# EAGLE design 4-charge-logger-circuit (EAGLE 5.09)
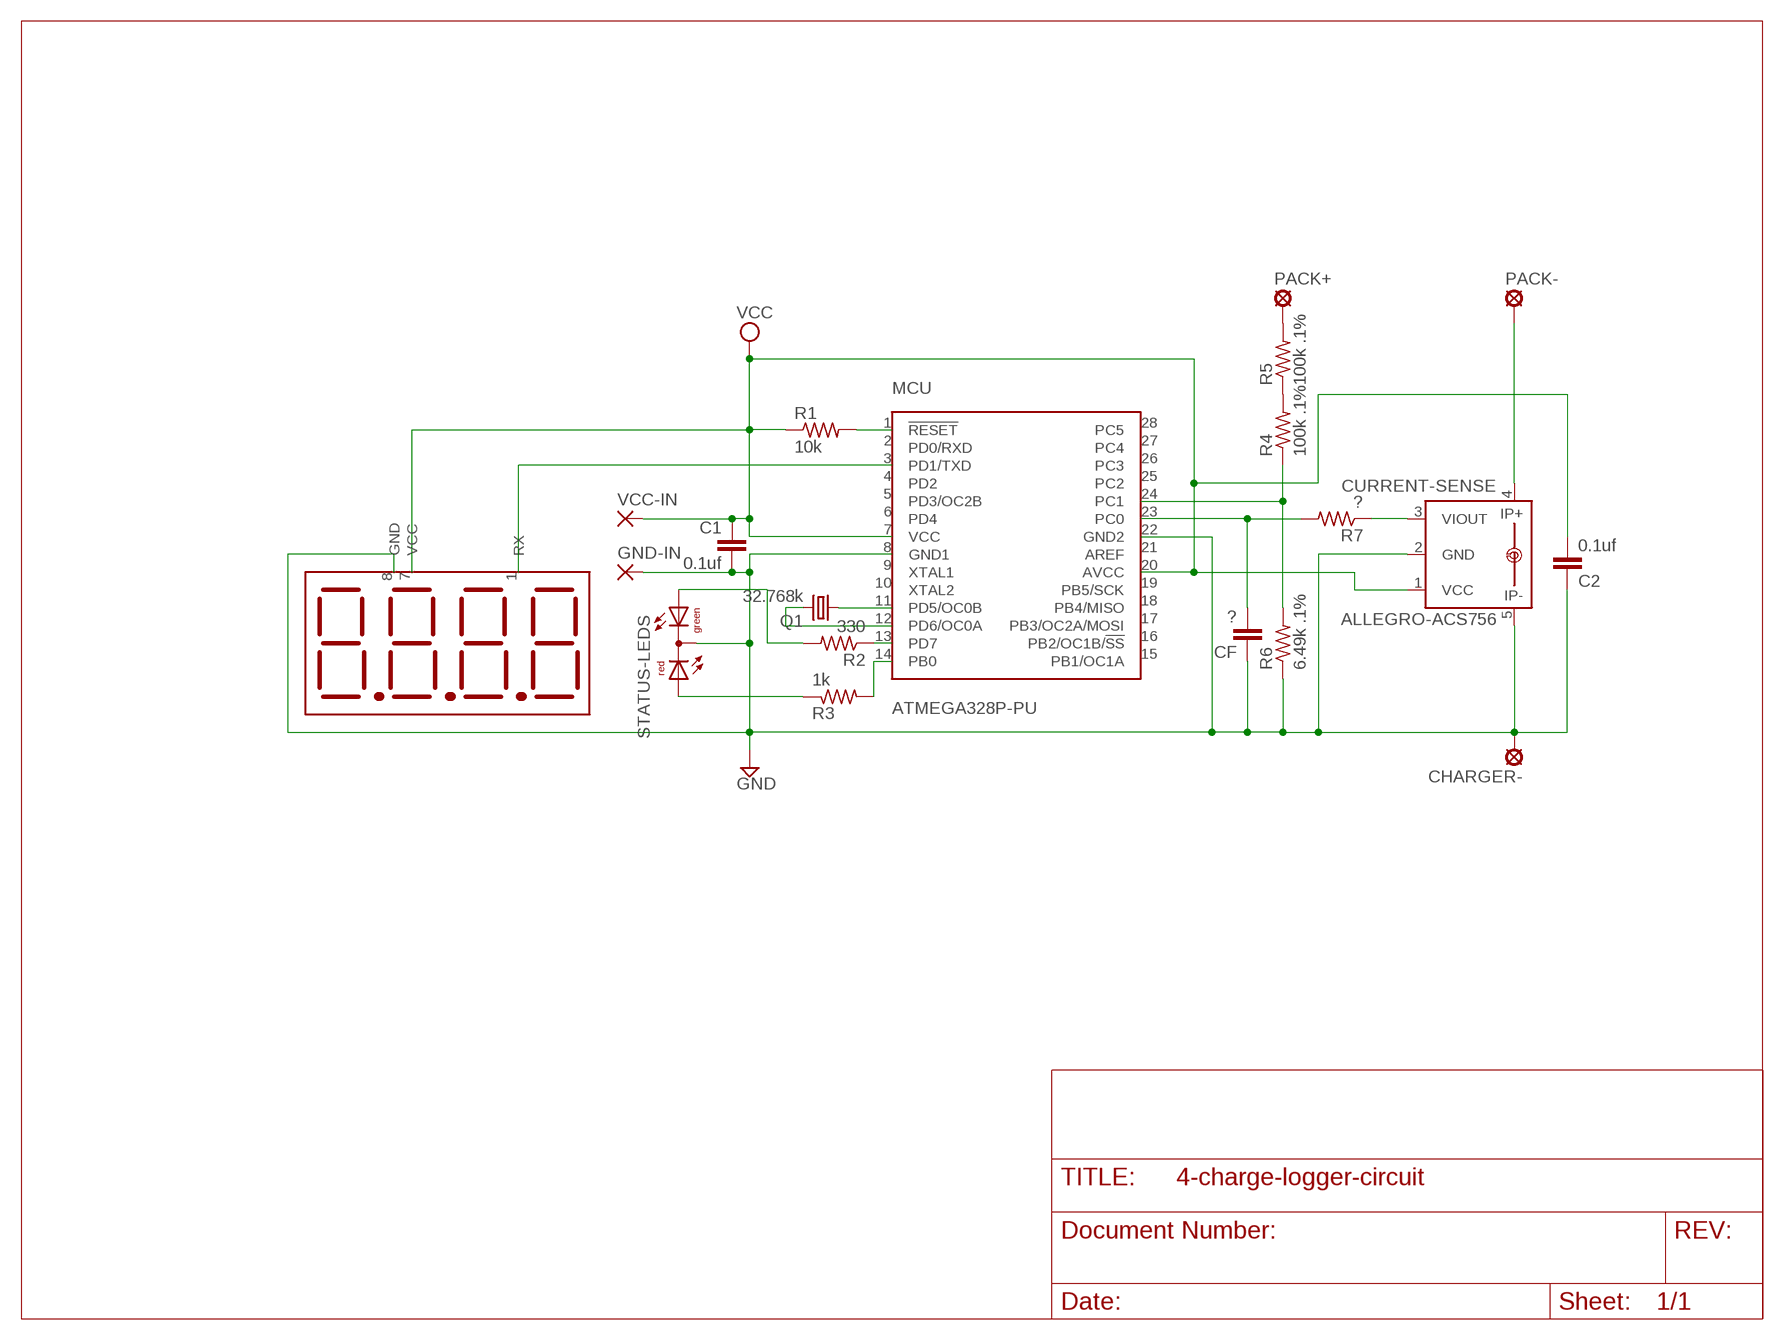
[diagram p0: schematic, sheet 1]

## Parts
C1  0.1uf  C2.5/2  [C2.5-2]
C2  0.1uf  C2.5/2  [C2.5-2]
CF  ?  C2.5/2  [C2.5-2]
CHARGER-  SE14  [SE14]
CURRENT-SENSE  ALLEGRO-ACS756  [ALLEGRO-ACS756]
GND-IN  1,6/0,8  [1,6/0,8]
MCU  ATMEGA328P-PU  [DIL28-3]
PACK+  SE14  [SE14]
PACK-  SE14  [SE14]
Q1  32.768k  CRYSTALTC26V  [TC26V]
R1  10k  R-US_0204/5  [0204/5]
R2  330  R-US_0204/5  [0204/5]
R3  1k  R-US_0204/5  [0204/5]
R4  100k .1%  R-US_R0805  [R0805]
R5  100k .1%  R-US_R0805  [R0805]
R6  6.49k .1%  R-US_R0402  [R0402]
R7  ?  R-US_0204/5  [0204/5]
STATUS-LEDS  DUOLED2X5  [DUOLED2X5]
U$1  4-DIGIT-DISPLAY  [3SIL-OF-8]
VCC-IN  1,6/0,8  [1,6/0,8]

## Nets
GND: C1.2 C2.1 CF.1 CHARGER-.MP CURRENT-SENSE.2(GND) CURRENT-SENSE.5(IP-) GND-IN.1(P) MCU.8(GND1) MCU.22(GND2) R6.1 STATUS-LEDS.K(C) U$1.8(GND)
N$1: MCU.1(!RESET) R1.2
N$2: MCU.12(PD6/OC0A) Q1.2
N$3: MCU.11(PD5/OC0B) Q1.1
N$4: MCU.13(PD7) R2.1
N$5: R3.1 STATUS-LEDS.AR
N$6: R2.2 STATUS-LEDS.AG
N$7: MCU.14(PB0) R3.2
N$8: R4.2 R5.1
N$9: MCU.3(PD1/TXD) U$1.1(RX)
N$10: CF.2 MCU.23(PC0) R7.2
N$11: PACK+.MP R5.2
N$12: CURRENT-SENSE.3(VIOUT) R7.1
N$13: MCU.24(PC1) R4.1 R6.2
N$14: CURRENT-SENSE.4(IP+) PACK-.MP
VCC: C1.1 C2.2 CURRENT-SENSE.1(VCC) MCU.7(VCC) MCU.20(AVCC) R1.1 U$1.7(VCC) VCC-IN.1(P)
Unconnected: MCU.2(PD0/RXD) MCU.4(PD2) MCU.5(PD3/OC2B) MCU.6(PD4) MCU.9(XTAL1) MCU.10(XTAL2) MCU.15(PB1/OC1A) MCU.16(PB2/OC1B/!SS) MCU.17(PB3/OC2A/MOSI) MCU.18(PB4/MISO) MCU.19(PB5/SCK) MCU.21(AREF) MCU.25(PC2) MCU.26(PC3) MCU.27(PC4) MCU.28(PC5)

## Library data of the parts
C1 C2 CF = capacitor-wima:C: CAPACITOR
CHARGER- PACK+ PACK- = solpad:SE14: SOLDER PAD
CURRENT-SENSE = trl:ALLEGRO-ACS756
GND-IN VCC-IN = wirepad:1,6/0,8: THROUGH-HOLE PAD
MCU = trl:ATMEGA328P-PU
Q1 = crystal:CRYSTAL: CRYSTAL
R1-R7 = resistor:R-US_: RESISTOR, American symbol
STATUS-LEDS = led:DUOLED2X5: DUO LED 2 colors, 2.5 x 5 mm, recangle
U$1 = trl:4-DIGIT-DISPLAY

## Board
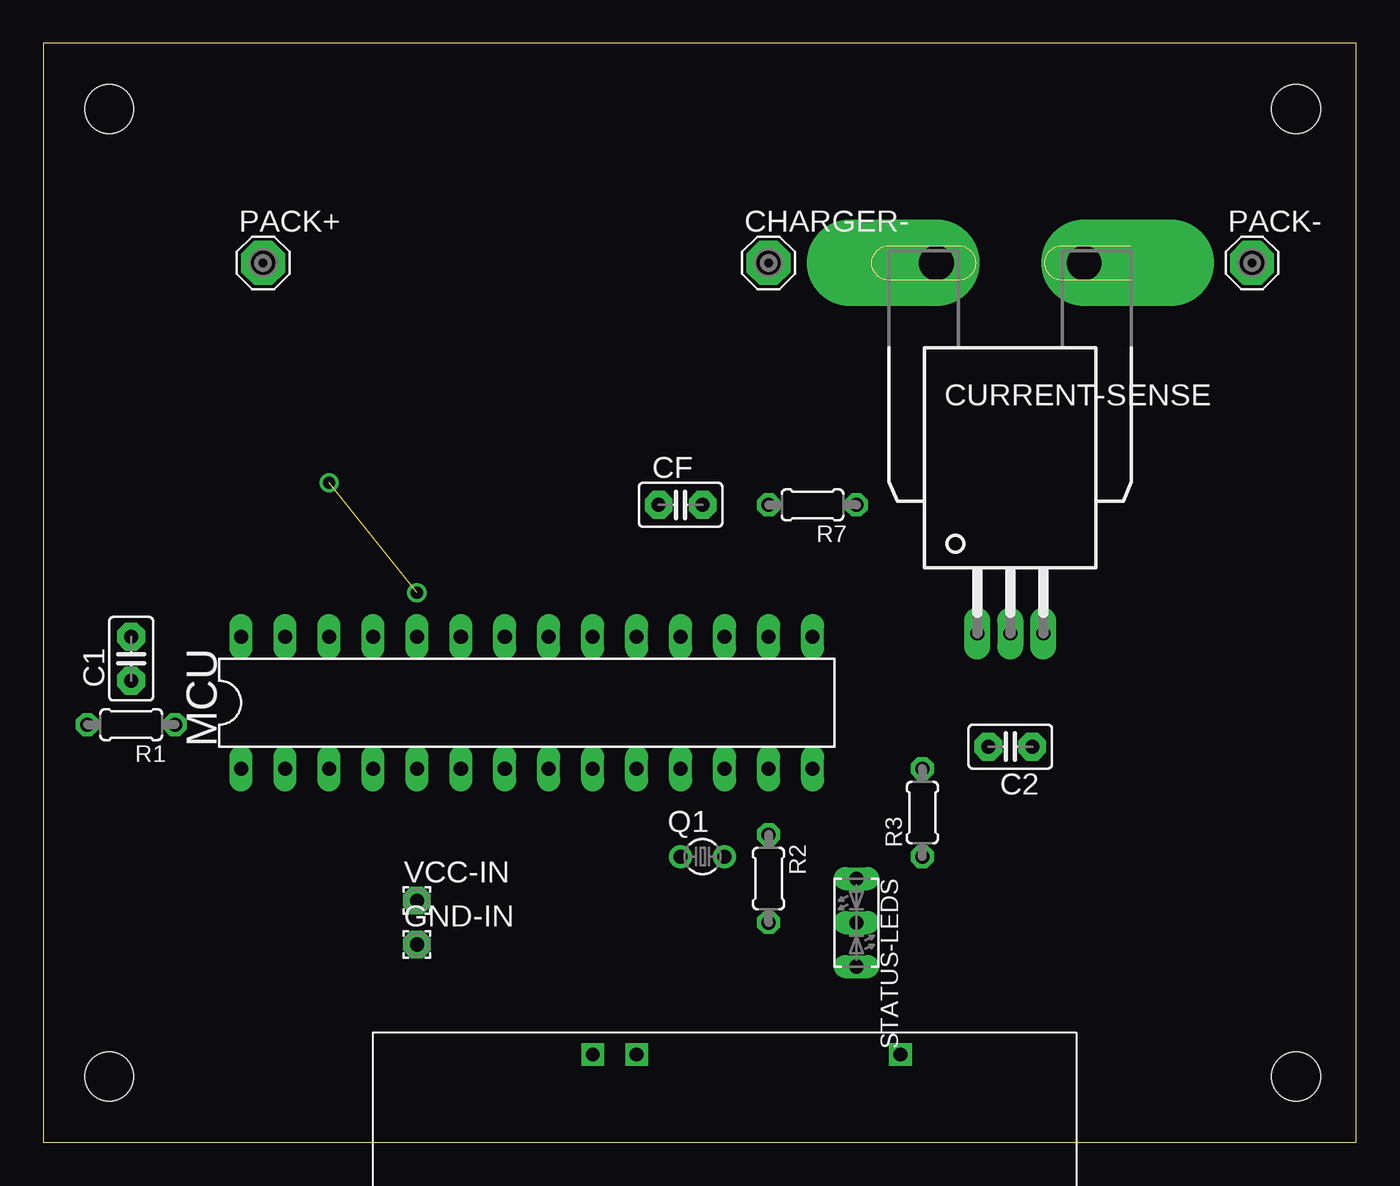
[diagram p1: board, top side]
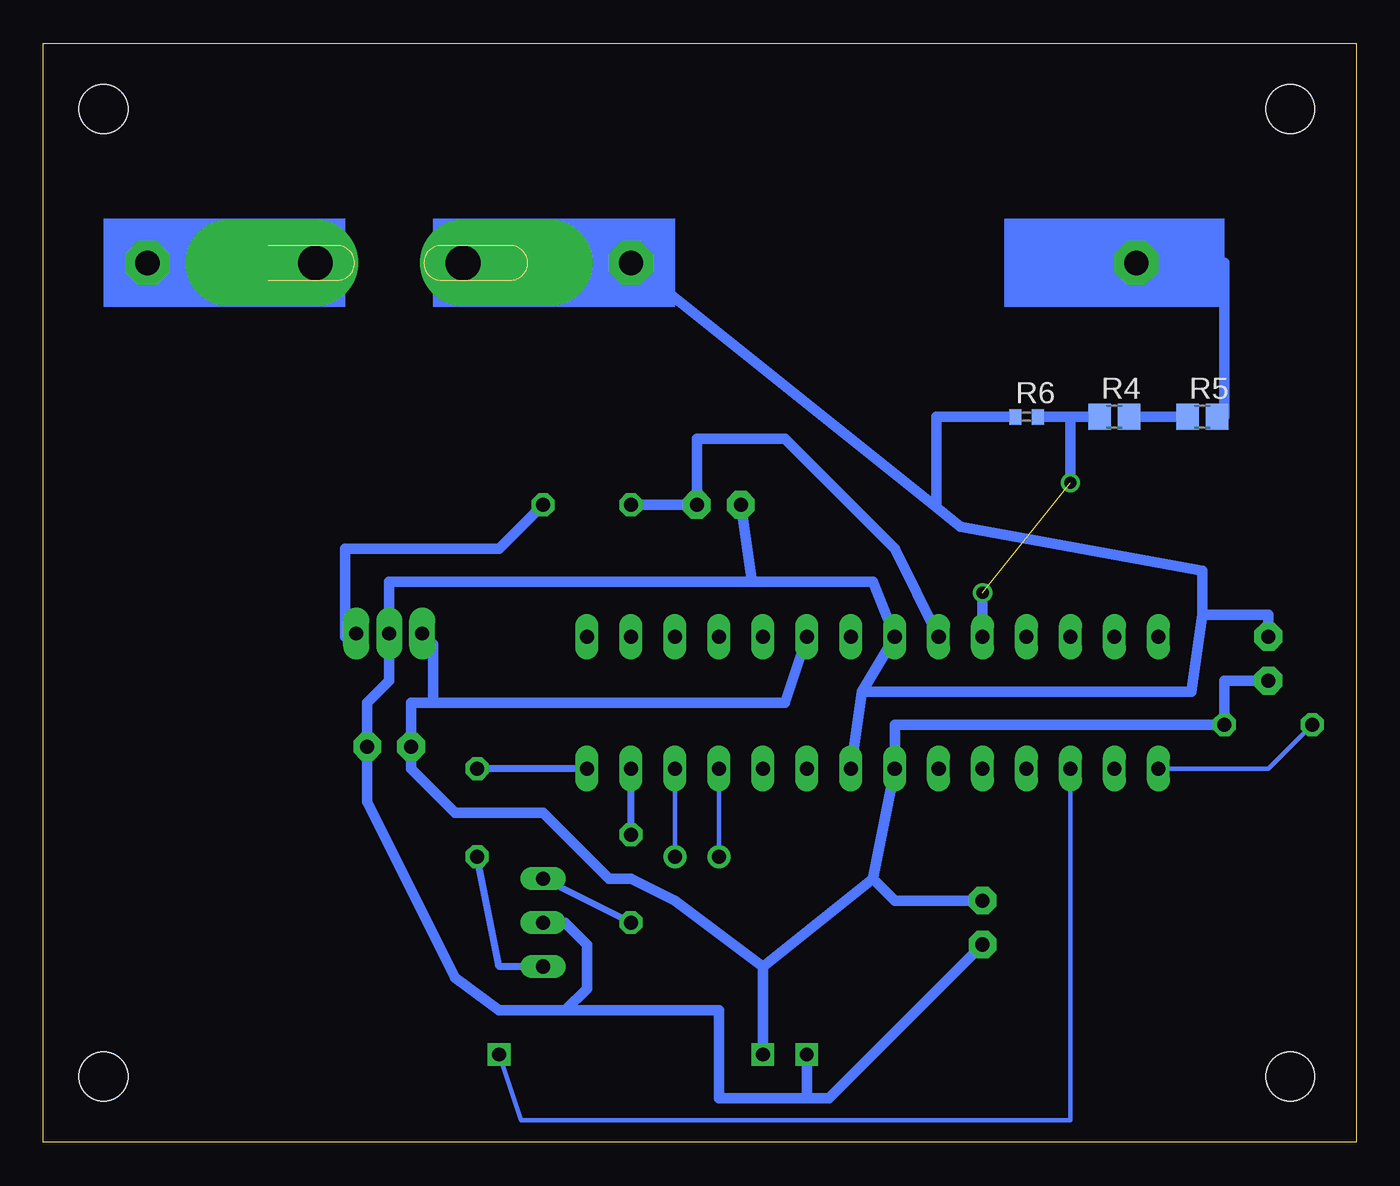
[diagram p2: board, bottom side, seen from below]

Size 75.87 x 63.49 mm. Coordinates in mm from the lower left corner, seen from the top.
Outline: 0,0 75.87,0 75.87,63.49 0,63.49 0,0
Copper layers (1*16): Top 0.035mm / dielectric 1.5mm / Bottom 0.035mm
Design rules "default": minimum track width 10mil, minimum drill 24mil, track to track 8mil, track to pad 8mil, pad to pad 8mil, via to via 8mil, smd to smd 8mil, copper to edge 40mil, drill to drill 8mil, minimum pad ring 10mil, minimum via ring 8mil, stop-mask expansion 4mil, vias tented up to drill 0mil, thermal gap 10mil
Holes 2.8 mm at 3.81,3.81 3.81,59.69 72.39,59.69 72.39,3.81

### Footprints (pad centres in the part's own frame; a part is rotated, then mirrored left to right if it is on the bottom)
C2.5-2 = drill 0.813 pad 1.6 octagon: 1 -1.27,0; 2 1.27,0
SE14 = drill 1.397 pad 2.54 octagon: MP 0,0
ALLEGRO-ACS756 = drill 0.8 pad 1.5 long: 1 -1.91,-11.24; 2 0,-11.24; 3 1.91,-11.24 | drill 2 pad 5 offset: 4 4.27,10.16; 5 -4.27,10.16
1,6/0,8 = drill 0.813 pad 1.6 octagon: 1 0,0
DIL28-3 = drill 0.813 long: 1 -16.51,-3.81; 2 -13.97,-3.81; 3 -11.43,-3.81; 4 -8.89,-3.81; 5 -6.35,-3.81; 6 -3.81,-3.81; 7 -1.27,-3.81; 8 1.27,-3.81; 9 3.81,-3.81; 10 6.35,-3.81; 11 8.89,-3.81; 12 11.43,-3.81; 13 13.97,-3.81; 14 16.51,-3.81; 15 16.51,3.81; 16 13.97,3.81; 17 11.43,3.81; 18 8.89,3.81; 19 6.35,3.81; 20 3.81,3.81; 21 1.27,3.81; 22 -1.27,3.81; 23 -3.81,3.81; 24 -6.35,3.81; 25 -8.89,3.81; 26 -11.43,3.81; 27 -13.97,3.81; 28 -16.51,3.81
TC26V = drill 0.813 round: 1 -1.27,0; 2 1.27,0
0204/5 = drill 0.813 octagon: 1 -2.54,0; 2 2.54,0
R0805 = smd 1.3 x 1.5: 1 -0.85,0; 2 0.85,0
R0402 = smd 0.7 x 0.9: 1 -0.65,0; 2 0.65,0
DUOLED2X5 = drill 0.813 long: AG -2.54,0; AR 2.54,0; K 0,0
3SIL-OF-8 = drill 0.8 square: 1 30.48,-1.27; 7 15.24,-1.27; 8 12.7,-1.27

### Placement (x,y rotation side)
C1  5.08,27.94 90 top
C2  55.88,22.86 180 top
CF  36.83,36.83 0 top
CHARGER-  41.91,50.8 0 top
CURRENT-SENSE  55.88,40.64 0 top
GND-IN  21.59,11.43 0 top
MCU  27.94,25.4 0 top
PACK+  12.7,50.8 0 top
PACK-  69.85,50.8 0 top
Q1  38.1,16.51 0 top
R1  5.08,24.13 180 top
R2  41.91,15.24 270 top
R3  50.8,19.05 90 top
R4  13.97,41.91 0 bottom
R5  8.89,41.91 0 bottom
R6  19.05,41.91 0 bottom
R7  44.45,36.83 180 top
STATUS-LEDS  46.99,12.7 270 top
U$1  19.05,6.35 0 top
VCC-IN  21.59,13.97 0 top

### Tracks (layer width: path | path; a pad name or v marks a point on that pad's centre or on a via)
GND
  Bottom 0.254: CHARGER-.MP CURRENT-SENSE.5
  Bottom 0.61: 28.57,26.04 MCU.8 | 28.57,26.04 MCU.22 27.94,32.38 34.92,32.38 | C1.2 5.08,30.48 8.89,30.48 | 8.89,30.48 9.53,26.04 28.57,26.04 | 24.25,36.67 22.86,35.56 8.89,33.02 8.89,30.48 | 24.25,36.67 CHARGER-.MP | 34.92,32.38 55.88,32.38 CURRENT-SENSE.2 55.88,26.67 57.15,25.4 C2.1 57.15,19.68 52.07,9.53 49.53,7.62 45.72,7.62 | R6.1 24.25,41.91 24.25,36.67 | STATUS-LEDS.K 45.72,12.7 44.45,11.43 44.45,8.89 45.72,7.62 | 34.92,32.38 CF.1 | 45.72,7.62 36.83,7.62 36.83,2.54 31.75,2.54 | 31.75,2.54 U$1.8 | 31.75,2.54 30.48,2.54 GND-IN.1
N$1
  Bottom 0.254: R1.2 5.08,21.59 MCU.1
N$2
  Bottom 0.254: Q1.2 MCU.12
N$3
  Bottom 0.254: Q1.1 MCU.11
N$4
  Bottom 0.406: R2.1 MCU.13
N$5
  Bottom 0.406: STATUS-LEDS.AR 49.53,10.16 R3.1
N$6
  Bottom 0.406: R2.2 STATUS-LEDS.AG
N$7
  Bottom 0.406: MCU.14 R3.2
N$8
  Bottom 0.61: R5.1 R4.2
N$9
  Bottom 0.254: U$1.1 48.26,1.27 16.51,1.27 MCU.3
N$10
  Bottom 0.61: MCU.23 26.67,34.29 33.02,40.64 38.1,40.64 CF.2 R7.2
N$11
  Bottom 0.254: 7.62,50.8 PACK+.MP | R5.2 7.62,41.91
  Bottom 0.61: 7.62,41.91 7.62,50.8
N$12
  Bottom 0.254: 58.42,29.21 CURRENT-SENSE.3
  Bottom 0.61: 58.42,29.21 58.42,34.29 49.53,34.29 R7.1
N$13  (1 unrouted)
  Bottom 0.61: R4.1 16.51,41.91 | 16.51,41.91 16.51,38.1 | 16.51,41.91 R6.2 | MCU.24 21.59,31.75
N$14
  Bottom 0.254: CURRENT-SENSE.4 PACK-.MP
N$15  (via drill 0.7)
  other vias: 16.51,38.1
N$16  (via drill 0.7)
  other vias: 21.59,31.75
VCC
  Bottom 0.254: CURRENT-SENSE.1 54.61,29.21
  Bottom 0.61: C1.1 7.62,26.67 R1.1 26.67,24.13 MCU.7 27.94,15.24 | 27.94,15.24 34.29,10.16 | MCU.20 33.02,25.4 53.34,25.4 | 53.34,25.4 54.61,25.4 C2.2 54.61,21.59 52.07,19.05 46.99,19.05 43.18,15.24 41.91,15.24 39.37,13.97 34.29,10.16 | 53.34,25.4 53.34,28.77 CURRENT-SENSE.1 | 34.29,10.16 U$1.7 | VCC-IN.1 26.67,13.97 27.94,15.24
(copper drawn outside any net)
  shapes: Bottom area x3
